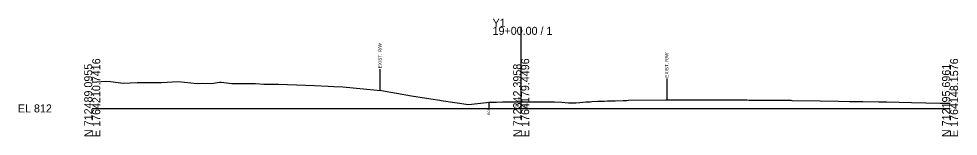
# Model space of a CAD drawing. Extents: x -26 to 1303, y -10 to 9524.
# Drawn here: x -25.7 to 302.8, y 8990.3 to 9031.3 of the extents above; entities that cross this region are included whole.
import ezdxf

# ---------------------------------------------------------------- set-up
doc = ezdxf.new("R2010")
doc.units = 0
for name, color, linetype in [('Default', 7, 'Continuous'), ('Exist Cross Section Cell', 7, 'Continuous'), ('Exist XS Center Line Elevation Label', 7, 'Continuous'), ('Exist XS Ground Line', 7, 'Continuous'), ('Old_Level_10', 7, 'Continuous')]:
    doc.layers.add(name, color=color, linetype=linetype)

msp = doc.modelspace()

# ---------------------------------------------------------------- linework, layer by layer
at = {"layer": 'Exist Cross Section Cell'}
for p, q in [((150, 9000), (150, 9028.5)), ((0, 9000), (150, 9000)), ((150, 9000), (300, 9000))]:
    msp.add_line(p, q, dxfattribs=at)
at = {"layer": 'Exist XS Ground Line'}
msp.add_lwpolyline([(0, 9009.19), (4.71, 9009.5), (6.34, 9009.44), (10.76, 9008.81), (15.7, 9009.05), (18.49, 9009.11), (24.23, 9009.1), (30.1, 9009.46), (36.74, 9008.76), (38.63, 9008.77), (41.72, 9008.76), (44.49, 9009.21), (45.13, 9009.15), (48.84, 9008.75), (57.04, 9008.66), (60.06, 9008.52), (63.44, 9008.52), (65.16, 9008.44), (77.67, 9008.06), (82.48, 9007.73), (84.5, 9007.67), (87.61, 9007.54), (99.59, 9006.4), (101.18, 9006.26), (111.61, 9004.45), (118.37, 9003.31), (121.53, 9002.87), (122, 9002.79), (131.6, 9001.42), (137.87, 9002.1), (138.69, 9002.2), (140.37, 9002.22), (141.02, 9002.24), (141.37, 9002.24), (143.5, 9002.26), (144.08, 9002.27), (146.06, 9002.31), (147.33, 9002.32), (148.62, 9002.33), (149.55, 9002.34), (150, 9002.35), (150.46, 9002.35), (150.81, 9002.35), (151.15, 9002.36), (153.73, 9002.33), (155.77, 9002.34), (156.28, 9002.35), (157.88, 9002.31), (158.84, 9002.28), (159.66, 9002.28), (161.11, 9002.29), (161.62, 9002.27), (164.2, 9002.16), (165.34, 9002.07), (166.51, 9001.98), (166.83, 9001.98), (169.07, 9001.99), (170.52, 9002.1), (171.62, 9002.19), (172.62, 9002.25), (174.18, 9002.34), (174.73, 9002.37), (176.84, 9002.48), (177.32, 9002.5), (179.07, 9002.56), (180.23, 9002.6), (181.95, 9002.65), (182.86, 9002.68), (185.63, 9002.75), (186.46, 9002.77), (186.97, 9002.81), (187.56, 9002.84), (200.63, 9003.01), (202.17, 9003.01), (213.59, 9003.01), (215.81, 9003.01), (216.4, 9003.03), (219.26, 9003), (225.48, 9003), (226.5, 9003), (229.07, 9003), (229.72, 9002.92), (243.27, 9002.83), (243.84, 9002.83), (244.27, 9002.83), (244.66, 9002.82), (254.57, 9002.66), (261.01, 9002.53), (264.8, 9002.47), (269.43, 9002.41), (275.03, 9002.34), (277.86, 9002.34), (286.54, 9002.02), (296.55, 9001.86), (298.13, 9001.83), (300, 9001.79)], dxfattribs=at)
at = {"layer": 'Old_Level_10'}
for p, q in [((100.6, 9013.71), (100.6, 9006.31)), ((200.92, 9010.41), (200.92, 9003.01)), ((138.69, 9002.2), (138.69, 9000.15))]:
    msp.add_line(p, q, dxfattribs=at)

# ---------------------------------------------------------------- texts
at = {"layer": 'Default'}
msp.add_text('-', height=0.0001, dxfattribs=at).set_placement((0, 9000))
at = {"layer": 'Exist Cross Section Cell'}
for s, p in [('Y1', (140, 9028.5)), ('19+00.00 / 1', (140, 9025.7)), ('EL 812', (-26, 8998.6))]:
    msp.add_text(s, height=2.8, dxfattribs=at).set_placement(p)
for s, p in [('N 712489.0955', (0, 8990)), ('E 1764210.7416', (2.8, 8990)), ('N 712342.3958', (150, 8990)), ('E 1764179.4496', (152.8, 8990)), ('N 712195.6961', (300, 8990)), ('E 1764148.1576', (302.8, 8990))]:
    msp.add_text(s, height=2.8, rotation=90, dxfattribs=at).set_placement(p)
at = {"layer": 'Exist XS Center Line Elevation Label'}
msp.add_text('814.35', height=1, dxfattribs=at).set_placement((147.99, 9000.35))
at = {"layer": 'Old_Level_10'}
for s, height, p in [('EXIST. R/W', 1.181, (101.19, 9014.02)), ('EXIST. R/W', 1.181, (201.51, 9010.71)), ('EOP', 0.787, (139.09, 8997.75))]:
    msp.add_text(s, height=height, rotation=90, dxfattribs=at).set_placement(p)

doc.saveas('drawing.dxf')
